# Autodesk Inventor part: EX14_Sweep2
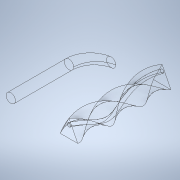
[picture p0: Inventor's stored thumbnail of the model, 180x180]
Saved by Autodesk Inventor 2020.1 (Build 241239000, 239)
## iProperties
Created: 2019-10
Part Number: EX14_Sweep2
Material: Generic
Document SubType Name: Modeling
Designer: Synergysoft Dell02
Density: 1 g/cm^3
Appearance: Default
Author: Synergysoft Dell02
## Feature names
1. Sweep1
2. Sweep3
## Parameters: d0 = 8 mm, d3 = 80 deg, d4 = 0, d5 = 0, d14 = 5 mm, d16 = 15 mm, d17 = 15 mm, d18 = 3 mm, d21 = 0, d22 = 360 deg
